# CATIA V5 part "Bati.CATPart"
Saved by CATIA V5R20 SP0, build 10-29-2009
Part number: Bati
Publications: "Axe_Pivot_bâtib11", "Axe_Pivot_bâtib3", "Axe_Pivot_bâtib111"
Bounding box of the stored display mesh (mm): x 0 to 300, y -440 to 0, z 0 to 20
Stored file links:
  C:\Users\Matthieu\Desktop\IFMA\Cours 2A\Thinkmotion\Bati.CATPart
  C:\Users\Matthieu\Desktop\IFMA\Cours 2A\Thinkmotion\skl_IAO_bis.CATProduct
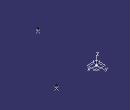
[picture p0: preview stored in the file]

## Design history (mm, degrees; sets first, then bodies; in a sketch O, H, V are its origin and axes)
AxisSystem1: origin (0, 0, 0), X (1, 0, 0), Y (0, 1, 0), Z (0, 0, 1)
Set1
  Plane1 "Plan_Ref": linked copy from another document
  Point1 "Point.A": linked copy from another document
  Point2 "Point.B": linked copy from another document
  Point3 "Point.G": linked copy from another document
Body1 (main body)
  Line1 "Axe_Pivot_bâtib11": type Normal, RefPoint Point1, RefSkin Plane1, Start 0, End 20
  Line2 "Axe_Pivot_bâtib3": type Normal, RefPoint Point2, RefSkin Plane1, Start 0, End 20
  Line3 "Axe_Pivot_bâtib1": type Normal, RefPoint Point3, RefSkin Plane1, Start 0, End 20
